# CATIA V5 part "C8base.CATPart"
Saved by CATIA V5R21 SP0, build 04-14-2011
Part number: C8base
Bounding box of the stored display mesh (mm): x -12.7 to 12.7, y 0 to 25.4, z 0 to 152.4
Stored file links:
  C:\Users\User\Desktop\B.D.M.A\Chapter8\C8base.CATPart
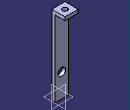
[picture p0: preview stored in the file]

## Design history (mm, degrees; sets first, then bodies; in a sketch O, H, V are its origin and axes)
Body1 (main body)
  Sketch1 on yz-plane, origin (0, 0, 0), H (0, 1, 0), V (0, 0, 1)
    line L1 (0, 0) -> (0, 152.4)
    line L2 (0, 152.4) -> (25.4, 152.4)
    line L3 (25.4, 152.4) -> (25.4, 146.05)
    line L4 (25.4, 146.05) -> (6.35, 146.05)
    line L5 (6.35, 146.05) -> (6.35, 0)
    line L6 (6.35, 0) -> (0, 0)
    length L1 = 152.4
    length L2 = 25.4
    length L3 = 6.35
    length L6 = 6.35
    vertical: L1 V, L3 V, L5 V
    horizontal: L2 H, L4 H, L6 H
  Pad1: profile Sketch1, direction (1, 0, 0), length 12.7, mirrored extent
  Sketch2 on face of Pad1 from Sketch1.L2, origin (0, 0, 152.4), H (1, 0, 0), V (0, 1, 0)
    circle A1 centre (0, 12.7) radius 5.08
    point P1 (0, 12.7)
    radius A1 = 5.08
    distance P1 H = 12.7
    coincidence: P1 V
  Pocket1: profile Sketch2, direction (0, 0, -1), through (limit type 6)
  Sketch3 on face of Pad1 from Sketch1.L5, origin (0, 6.35, 0), H (-1, 0, 0), V (0, 0, 1)
    circle A1 centre (0, 45) radius 7.62
    point P1 (0, 45)
    radius A1 = 7.62
    distance P1 H = 45
    coincidence: P1 V
  Pocket2: profile Sketch3, direction (0, -1, 0), through (limit type 6)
